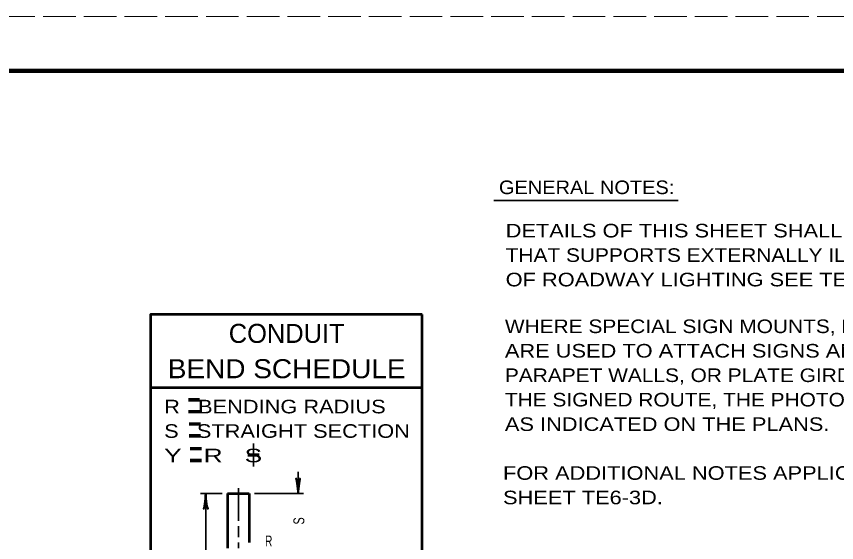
# Model space of a CAD drawing. Extents: x -68 to 612, y -58 to 382.
# Drawn here: x 265 to 416, y 285.4 to 382.2 of the extents above; entities that cross this region are included whole.
import ezdxf
from ezdxf.enums import TextEntityAlignment as Align

# ---------------------------------------------------------------- set-up
doc = ezdxf.new("R2010")
doc.units = 0
doc.linetypes.add('LONG_DASHED', pattern=[7.5, 6, -1.5])
doc.layers.add('1', color=7, linetype='Continuous', lineweight=53)
doc.layers.add('61', color=7, linetype='Continuous', lineweight=35)

msp = doc.modelspace()

# ---------------------------------------------------------------- linework, layer by layer
at = {"layer": '1', "lineweight": 35}
for p, q in [((352.849, 348.28), (386.822, 348.28)), ((316.841, 294.371), (316.841, 298.371)), ((305.841, 295.371), (305.841, 289.371)), ((302.841, 294.371), (298.841, 294.371)), ((299.841, 294.371), (299.841, 273.36)), ((308.841, 294.371), (317.841, 294.371)), ((305.841, 288.371), (305.841, 286.371)), ((305.841, 285.371), (305.841, 284.371))]:
    msp.add_line(p, q, dxfattribs=at)
at = {"layer": '1'}
for p, q in [((339.661, 313.811), (289.661, 313.811)), ((303.841, 294.371), (307.841, 294.371)), ((303.841, 294.371), (303.841, 284.371)), ((307.841, 294.371), (307.841, 285.371))]:
    msp.add_line(p, q, dxfattribs=at)
msp.add_lwpolyline([(339.661, 327.311), (289.661, 327.311), (289.661, 227.311), (339.661, 227.311)], close=True, dxfattribs=at)
at = {"layer": '1', "lineweight": 40}
for centre, major_axis, ratio, start_param, end_param in [((316.564, 295.462), (0.156, -1.786), 0.122415, 0.8963533, 3.1415927), ((316.564, 295.462), (0.156, -1.786), 0.122415, 0.8963533, 3.1415927), ((317.052, 295.492), (-0.176, -1.756), 0.07063, 3.1407148, 5.41811), ((317.052, 295.492), (-0.176, -1.756), 0.07063, 3.1407148, 5.41811), ((299.629, 293.25), (0.176, 1.756), 0.07063, 3.1407148, 5.41811), ((299.629, 293.25), (0.176, 1.756), 0.07063, 3.1407148, 5.41811), ((300.117, 293.28), (-0.156, 1.786), 0.122415, 0.8963533, 3.1415927), ((300.117, 293.28), (-0.156, 1.786), 0.122415, 0.8963533, 3.1415927)]:
    msp.add_ellipse(centre, major_axis=major_axis, ratio=ratio, start_param=start_param, end_param=end_param, dxfattribs=at)
at = {"layer": '61', "linetype": 'LONG_DASHED', "lineweight": 13}
msp.add_line((-67.611, 382.166), (612.409, 382.166), dxfattribs=at)
at = {"layer": '61', "lineweight": 158}
msp.add_lwpolyline([(601.429, 372.166), (-37.611, 372.166), (-37.611, -47.854)], dxfattribs=at)

# ---------------------------------------------------------------- texts
at = {"layer": '1'}
for s, height, width, p in [('GENERAL NOTES:', 2.5, 1.1, (369.957, 349.475)), ('BEND SCHEDULE', 3.5, 1.1, (314.735, 315.606)), ('=', 6, 0.55, (297.673, 307.667)), ('=', 6, 0.55, (297.841, 303.231)), ('+', 6, 0.55, (308.618, 298.571)), ('=', 6, 0.55, (298.009, 298.683))]:
    msp.add_text(s, height=height, dxfattribs=dict(at, width=width)).set_placement(p, align=Align.CENTER)
for s, height, width, p in [('DETAILS OF THIS SHEET SHALL APPLY TO EACH OVERHEAD SIGN STRUCTURE', 2.5, 1.2, (355.053, 341.506)), ('THAT SUPPORTS EXTERNALLY ILLUMINATED SIGNS (WHEN SIGN LIGHTING PART', 2.5, 1.15, (355.053, 337.006)), ('OF ROADWAY LIGHTING SEE TEL-06).', 2.5, 1.2, (355.053, 332.506)), ('WHERE SPECIAL SIGN MOUNTS, FABRICATED FROM STRUCTURAL STEEL,', 2.5, 1.15, (354.908, 323.909)), ('ARE USED TO ATTACH SIGNS AND SIGN LIGHTING TO THE SUPERSTRUCTURE,', 2.5, 1.2, (354.908, 319.409)), ('PARAPET WALLS, OR PLATE GIRDERS OF ROADWAY BRIDGES OVERPASSING', 2.5, 1.15, (354.908, 314.909)), ('THE SIGNED ROUTE, THE PHOTOELECTRIC CONTROL UNIT SHALL BE INSTALLED', 2.5, 1.15, (354.908, 310.409)), ('R   BENDING RADIUS', 2.5, 1.2, (292.176, 309.143)), ('AS INDICATED ON THE PLANS.', 2.5, 1.2, (354.908, 305.909)), ('S   STRAIGHT SECTION', 2.5, 1.2, (292.176, 304.643)), ('Y   R   S', 2.5, 1.45, (292.176, 300.143)), ('FOR ADDITIONAL NOTES APPLICABLE TO THIS SHEET REFER TO STANDARD', 2.5, 1.2, (354.565, 296.92)), ('SHEET TE6-3D.', 2.5, 1.2, (354.565, 292.42)), ('R', 2, 0.7, (310.75, 284.654))]:
    msp.add_text(s, height=height, dxfattribs=dict(at, width=width)).set_placement(p)
msp.add_text('CONDUIT', height=3.5, dxfattribs=at).set_placement((314.735, 322.106), align=Align.CENTER)
at = {"layer": '1', "width": 0.75}
msp.add_text('S', height=2, rotation=90, dxfattribs=at).set_placement((317.974, 288.688))

doc.saveas('drawing.dxf')
